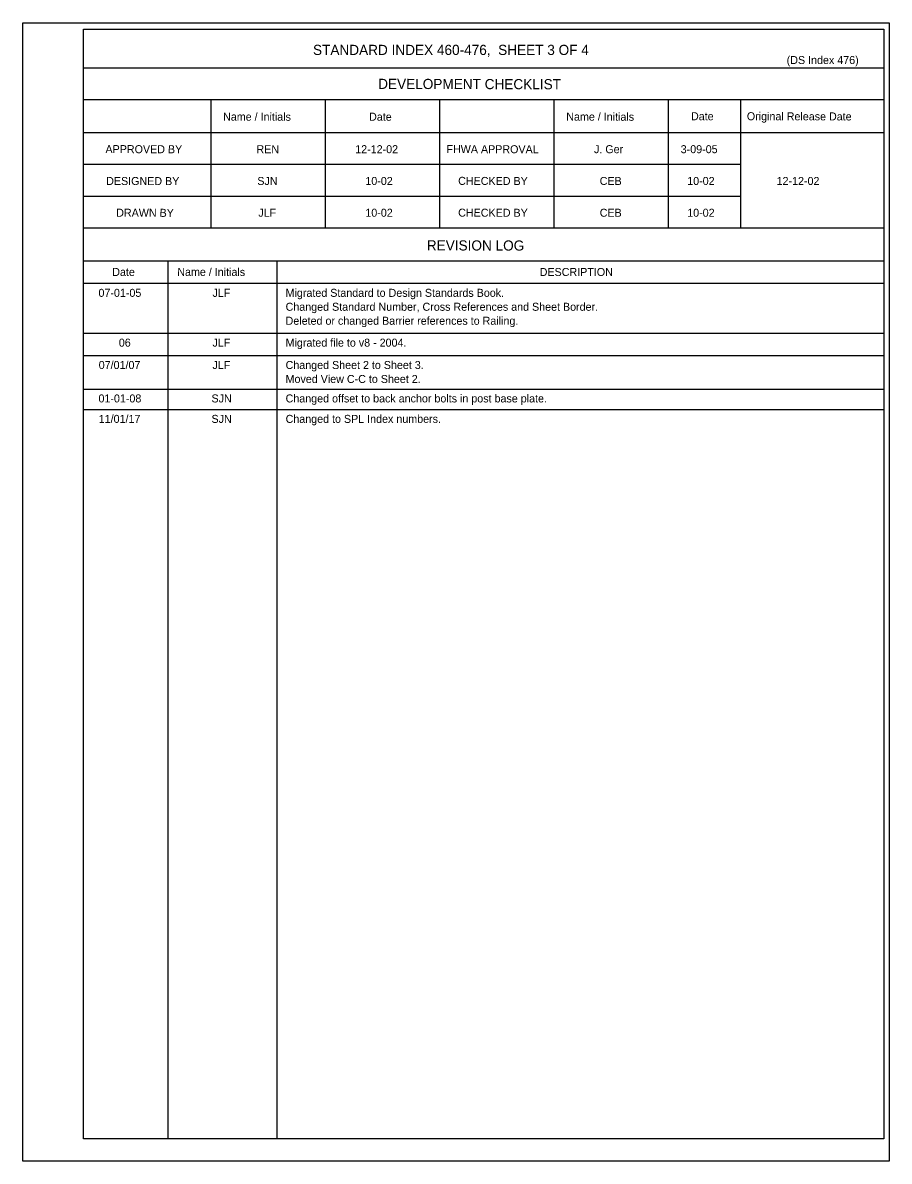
# Model space of a CAD drawing. Extents: x 21526.6 to 21598.7, y 56118.1 to 56155.9.
# Drawn here: x 21576.91 to 21598.72, y 56124.63 to 56153.3 of the extents above; entities that cross this region are included whole.
import ezdxf

# ---------------------------------------------------------------- set-up
doc = ezdxf.new("R2010")
doc.units = 0
doc.layers.add('Border', color=7, linetype='Continuous')
doc.layers.add('PlotBorder_dp', color=7, linetype='Continuous')

msp = doc.modelspace()

# ---------------------------------------------------------------- linework, layer by layer
at = {"layer": 'Border'}
for p, q in [((21598.589, 56152.158), (21578.442, 56152.158)), ((21598.589, 56151.358), (21578.442, 56151.358)), ((21581.642, 56151.358), (21581.642, 56148.13)), ((21584.522, 56151.358), (21584.522, 56148.13)), ((21587.402, 56151.358), (21587.402, 56148.13)), ((21590.282, 56151.358), (21590.282, 56148.13)), ((21593.162, 56151.358), (21593.162, 56148.13)), ((21594.977, 56151.358), (21594.977, 56148.13)), ((21598.589, 56150.53), (21578.442, 56150.53)), ((21594.977, 56149.73), (21578.442, 56149.73)), ((21594.977, 56148.93), (21578.442, 56148.93)), ((21598.589, 56148.13), (21578.442, 56148.13)), ((21598.589, 56147.302), (21578.442, 56147.302)), ((21580.562, 56147.302), (21580.562, 56125.196)), ((21583.304, 56147.302), (21583.304, 56125.196)), ((21598.589, 56146.738), (21578.442, 56146.738))]:
    msp.add_line(p, q, dxfattribs=at)
msp.add_lwpolyline([(21578.442, 56153.138), (21598.589, 56153.138), (21598.589, 56125.196), (21578.442, 56125.196)], close=True, dxfattribs=at)
at = {"layer": 'PlotBorder_dp'}
for p, q in [((21578.442, 56145.484), (21598.589, 56145.484)), ((21578.442, 56144.921), (21598.589, 56144.921)), ((21578.442, 56144.079), (21598.589, 56144.079)), ((21578.442, 56143.565), (21598.589, 56143.565)), ((21576.911, 56124.634), (21576.911, 56124.634))]:
    msp.add_line(p, q, dxfattribs=at)
msp.add_lwpolyline([(21576.911, 56153.301), (21598.725, 56153.301), (21598.725, 56124.634), (21576.911, 56124.634)], close=True, dxfattribs=at)

# ---------------------------------------------------------------- texts
at = {"layer": 'Border'}
for s, height, p in [('STANDARD INDEX 460-476,  SHEET 3 OF 4', 0.256, (21584.218, 56152.49)), ('(DS Index 476)', 0.2016, (21596.143, 56152.262)), ('REN', 0.2016, (21582.794, 56150.017)), ('12-12-02', 0.2016, (21585.281, 56150.017)), ('J. Ger', 0.2016, (21591.292, 56150.017)), ('3-09-05', 0.2016, (21593.475, 56150.017)), ('SJN', 0.2016, (21582.816, 56149.217)), ('10-02', 0.2016, (21585.536, 56149.217)), ('CEB', 0.2016, (21591.436, 56149.217)), ('10-02', 0.2016, (21593.639, 56149.217)), ('12-12-02', 0.2016, (21595.889, 56149.217)), ('JLF', 0.2016, (21582.841, 56148.417)), ('10-02', 0.2016, (21585.536, 56148.417)), ('CEB', 0.2016, (21591.436, 56148.417)), ('10-02', 0.2016, (21593.639, 56148.417)), ('DESCRIPTION', 0.2016, (21589.925, 56146.925)), ('07-01-05', 0.2016, (21578.817, 56146.4)), ('JLF', 0.2016, (21581.688, 56146.4)), ('Migrated Standard to Design Standards Book.', 0.2016, (21583.528, 56146.4)), ('Changed Standard Number, Cross References and Sheet Border.', 0.2016, (21583.528, 56146.049)), ('Deleted or changed Barrier references to Railing.', 0.2016, (21583.528, 56145.697)), ('06', 0.2016, (21579.329, 56145.146)), ('JLF', 0.2016, (21581.688, 56145.146)), ('Migrated file to v8 - 2004.', 0.2016, (21583.528, 56145.146)), ('07/01/07', 0.2016, (21578.823, 56144.583)), ('JLF', 0.2016, (21581.688, 56144.583)), ('Changed Sheet 2 to Sheet 3.', 0.2016, (21583.528, 56144.583)), ('Moved View C-C to Sheet 2.', 0.2016, (21583.528, 56144.231)), ('01-01-08', 0.2016, (21578.817, 56143.741)), ('SJN', 0.2016, (21581.663, 56143.741)), ('Changed offset to back anchor bolts in post base plate.', 0.2016, (21583.528, 56143.741)), ('11/01/17', 0.2016, (21578.823, 56143.226)), ('SJN', 0.2016, (21581.663, 56143.226)), ('Changed to SPL Index numbers.', 0.2016, (21583.528, 56143.226))]:
    msp.add_text(s, height=height, dxfattribs=at).set_placement(p)
for s, height, p in [('DEVELOPMENT CHECKLIST', 0.256, (21585.858, 56151.635)), ('Name / Initials', 0.2016, (21581.954, 56150.837)), ('Date', 0.2016, (21585.629, 56150.835)), ('Name / Initials', 0.2016, (21590.594, 56150.837)), ('Date', 0.2016, (21593.734, 56150.847)), ('Original Release Date', 0.2016, (21595.14, 56150.847)), ('APPROVED BY', 0.2016, (21578.993, 56150.019)), ('FHWA APPROVAL', 0.2016, (21587.577, 56150.019)), ('DESIGNED BY', 0.2016, (21579.01, 56149.217)), ('CHECKED BY', 0.2016, (21587.872, 56149.219)), ('DRAWN BY', 0.2016, (21579.263, 56148.417)), ('CHECKED BY', 0.2016, (21587.872, 56148.419)), ('REVISION LOG', 0.256, (21587.083, 56147.569)), ('Date', 0.2016, (21579.164, 56146.926)), ('Name / Initials', 0.2016, (21580.801, 56146.928))]:
    msp.add_text(s, height=height, rotation=359.8756, dxfattribs=at).set_placement(p)

doc.saveas('drawing.dxf')
